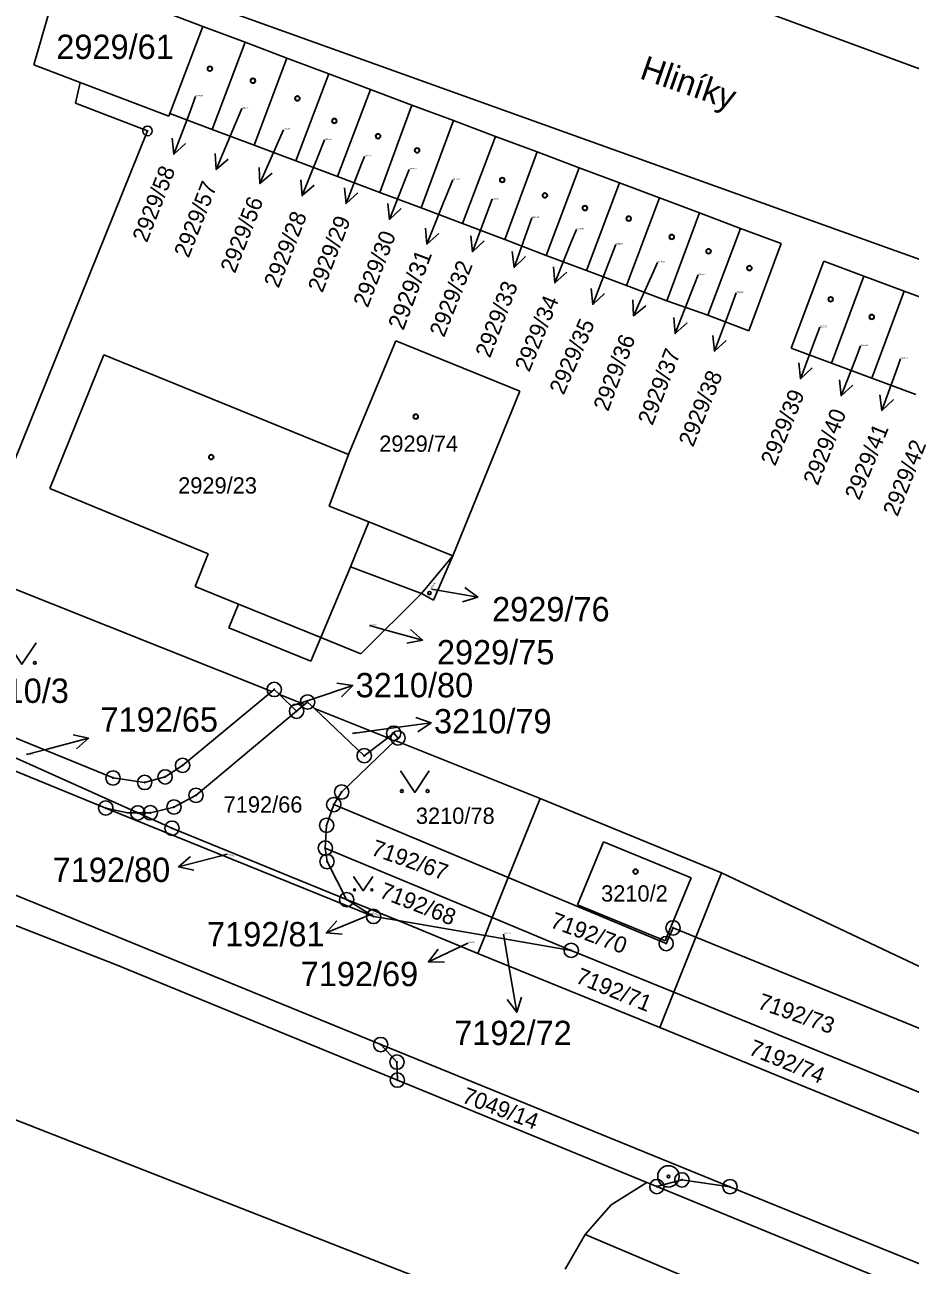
# Model space of a CAD drawing. Extents: x -593183 to -588034, y -1130415 to -1124994.
# Drawn here: x -592005.2 to -591943.3, y -1128267.2 to -1128180.5 of the extents above; entities that cross this region are included whole.
import ezdxf

# ---------------------------------------------------------------- set-up
doc = ezdxf.new("R2010")
doc.units = 0
for name, color, linetype in [('Vrstva 1', 7, 'Continuous'), ('Vrstva 15', 7, 'Continuous'), ('Vrstva 16', 7, 'Continuous'), ('Vrstva 18', 7, 'Continuous'), ('Vrstva 19', 7, 'Continuous'), ('Vrstva 24', 7, 'Continuous'), ('Vrstva 25', 7, 'Continuous'), ('Vrstva 4', 7, 'Continuous')]:
    doc.layers.add(name, color=color, linetype=linetype)

msp = doc.modelspace()

# ---------------------------------------------------------------- linework, layer by layer
at = {"layer": 'Vrstva 1'}
for p, q in [((-591999.24, -1128162.62), (-591935.86, -1128186.03)), ((-592002.65, -1128176.79), (-592004.53, -1128183.25)), ((-591999.4, -1128176.48), (-591937.35, -1128198.75)), ((-591999.73, -1128177.9), (-591992.72, -1128180.57)), ((-591992.72, -1128180.57), (-591995.01, -1128186.66)), ((-591992.72, -1128180.57), (-591989.76, -1128181.68)), ((-591989.76, -1128181.68), (-591992.05, -1128187.77)), ((-591989.76, -1128181.68), (-591986.83, -1128182.79)), ((-592004.53, -1128183.25), (-592001.28, -1128184.49)), ((-591986.83, -1128182.79), (-591989.12, -1128188.87)), ((-591983.9, -1128183.89), (-591986.83, -1128182.79)), ((-591986.21, -1128189.97), (-591983.9, -1128183.89)), ((-591983.9, -1128183.89), (-591980.99, -1128184.98)), ((-592001.28, -1128184.49), (-592001.62, -1128185.95)), ((-592001.28, -1128184.49), (-591995.08, -1128186.84)), ((-591980.99, -1128184.98), (-591983.3, -1128191.07)), ((-591980.99, -1128184.98), (-591978.09, -1128186.07)), ((-592001.62, -1128185.95), (-591996.58, -1128187.88)), ((-591995.08, -1128186.84), (-591995.01, -1128186.66)), ((-591995.01, -1128186.66), (-591992.05, -1128187.77)), ((-591978.09, -1128186.07), (-591980.35, -1128192.18)), ((-591978.09, -1128186.07), (-591975.18, -1128187.16)), ((-591975.18, -1128187.16), (-591977.45, -1128193.26)), ((-591975.18, -1128187.16), (-591972.26, -1128188.26)), ((-591996.58, -1128187.88), (-592009.01, -1128218.65)), ((-591992.05, -1128187.77), (-591989.12, -1128188.87)), ((-591972.26, -1128188.26), (-591974.55, -1128194.35)), ((-591972.26, -1128188.26), (-591969.35, -1128189.35)), ((-591989.12, -1128188.87), (-591986.21, -1128189.97)), ((-591969.35, -1128189.35), (-591971.59, -1128195.46)), ((-591969.35, -1128189.35), (-591966.4, -1128190.46)), ((-591983.3, -1128191.07), (-591986.21, -1128189.97)), ((-591980.35, -1128192.18), (-591983.3, -1128191.07)), ((-591966.4, -1128190.46), (-591968.7, -1128196.59)), ((-591966.4, -1128190.46), (-591963.59, -1128191.51)), ((-591963.59, -1128191.51), (-591965.89, -1128197.64)), ((-591963.59, -1128191.51), (-591960.79, -1128192.56)), ((-591977.45, -1128193.26), (-591980.35, -1128192.18)), ((-591960.79, -1128192.56), (-591963.09, -1128198.69)), ((-591960.79, -1128192.56), (-591957.98, -1128193.61)), ((-591974.55, -1128194.35), (-591977.45, -1128193.26)), ((-591960.28, -1128199.75), (-591957.98, -1128193.61)), ((-591957.98, -1128193.61), (-591955.13, -1128194.69)), ((-591971.59, -1128195.46), (-591974.55, -1128194.35)), ((-591968.7, -1128196.59), (-591971.59, -1128195.46)), ((-591955.13, -1128194.69), (-591957.41, -1128200.77)), ((-591955.13, -1128194.69), (-591952.27, -1128195.76)), ((-591952.27, -1128195.76), (-591954.55, -1128201.85)), ((-591965.89, -1128197.64), (-591968.7, -1128196.59)), ((-591949.3, -1128196.98), (-591951.57, -1128203.07)), ((-591946.49, -1128198.03), (-591949.3, -1128196.98)), ((-591963.09, -1128198.69), (-591965.89, -1128197.64)), ((-591948.76, -1128204.12), (-591946.49, -1128198.03)), ((-591946.49, -1128198.03), (-591943.68, -1128199.08)), ((-591963.09, -1128198.69), (-591960.28, -1128199.75)), ((-591960.28, -1128199.75), (-591957.41, -1128200.77)), ((-591943.68, -1128199.08), (-591945.95, -1128205.17)), ((-591943.68, -1128199.08), (-591940.6, -1128200.22)), ((-591954.55, -1128201.85), (-591957.41, -1128200.77)), ((-591982.53, -1128210.49), (-591979.23, -1128202.56)), ((-591979.23, -1128202.56), (-591970.54, -1128206.08)), ((-591951.57, -1128203.07), (-591948.76, -1128204.12)), ((-591999.63, -1128203.53), (-592003.42, -1128212.88)), ((-591999.63, -1128203.53), (-591982.53, -1128210.49)), ((-591945.95, -1128205.17), (-591948.76, -1128204.12)), ((-591945.95, -1128205.17), (-591942.86, -1128206.31)), ((-591970.54, -1128206.08), (-591975.24, -1128217.57)), ((-591982.53, -1128210.49), (-591983.87, -1128214.1)), ((-592003.42, -1128212.88), (-591992.35, -1128217.45)), ((-591983.87, -1128214.1), (-591981.1, -1128215.21)), ((-591981.1, -1128215.21), (-591982.38, -1128218.36)), ((-592042.06, -1128217.83), (-591999.5, -1128235.21)), ((-591992.35, -1128217.45), (-591993.25, -1128219.73)), ((-591975.24, -1128217.57), (-591977.42, -1128220.22)), ((-591976.58, -1128220.68), (-591975.24, -1128217.57)), ((-592009.01, -1128218.65), (-591987.9, -1128227.07)), ((-591982.38, -1128218.36), (-591984.47, -1128223.3)), ((-591982.38, -1128218.36), (-591977.42, -1128220.22)), ((-591993.25, -1128219.73), (-591990.22, -1128220.96)), ((-591977.42, -1128220.22), (-591981.67, -1128224.44)), ((-591977.42, -1128220.22), (-591976.58, -1128220.68)), ((-591990.22, -1128220.96), (-591990.9, -1128222.61)), ((-591990.9, -1128222.61), (-591985.16, -1128224.95)), ((-591985.16, -1128224.95), (-591984.47, -1128223.3)), ((-591984.47, -1128223.3), (-591981.67, -1128224.44)), ((-592012.61, -1128227.55), (-591998.99, -1128233.11)), ((-591994.13, -1128232.23), (-591987.9, -1128227.07)), ((-591987.9, -1128227.07), (-591987.72, -1128226.92)), ((-591987.72, -1128226.92), (-591987.35, -1128227.28)), ((-591987.35, -1128227.28), (-591986.16, -1128228.44)), ((-591985.6, -1128227.98), (-591987.35, -1128227.28)), ((-591986.16, -1128228.44), (-591985.6, -1128227.98)), ((-591985.6, -1128227.98), (-591985.39, -1128227.8)), ((-591985.39, -1128227.8), (-591984.91, -1128228.26)), ((-591984.91, -1128228.26), (-591981.43, -1128231.55)), ((-591984.91, -1128228.26), (-591979.79, -1128230.3)), ((-592012.99, -1128228.49), (-591997.26, -1128235.55)), ((-591993.19, -1128234.32), (-591986.16, -1128228.44)), ((-592035.07, -1128229.36), (-591980.28, -1128251.74)), ((-591979.79, -1128230.3), (-591979.37, -1128229.98)), ((-591979.37, -1128229.98), (-591979.07, -1128230.31)), ((-592038.06, -1128230.79), (-591998.83, -1128246.15)), ((-591979.27, -1128230.5), (-591983.01, -1128234.09)), ((-591981.43, -1128231.55), (-591979.79, -1128230.3)), ((-591979.07, -1128230.31), (-591979.27, -1128230.5)), ((-591969.14, -1128234.54), (-591979.27, -1128230.5)), ((-591995.35, -1128233.03), (-591994.13, -1128232.23)), ((-591998.99, -1128233.11), (-591996.78, -1128233.42)), ((-591996.78, -1128233.42), (-591995.35, -1128233.03)), ((-591994.73, -1128235.14), (-591993.19, -1128234.32)), ((-591983.01, -1128234.09), (-591983.56, -1128234.97)), ((-591999.5, -1128235.21), (-591997.97, -1128235.55)), ((-591999.5, -1128235.21), (-591980.78, -1128242.79)), ((-591996.38, -1128235.54), (-591994.73, -1128235.14)), ((-591983.56, -1128234.97), (-591984.06, -1128236.42)), ((-591983.56, -1128234.97), (-591971.36, -1128240.07)), ((-591971.36, -1128240.07), (-591969.14, -1128234.54)), ((-591969.14, -1128234.54), (-591956.45, -1128239.73)), ((-591997.97, -1128235.55), (-591997.26, -1128235.55)), ((-591997.26, -1128235.55), (-591996.38, -1128235.54)), ((-591997.26, -1128235.55), (-591994.87, -1128236.62)), ((-591994.87, -1128236.62), (-591982.66, -1128241.61)), ((-591984.06, -1128236.42), (-591984.15, -1128238.01)), ((-591984.15, -1128238.01), (-591984.03, -1128238.95)), ((-591984.15, -1128238.01), (-591972.48, -1128242.87)), ((-591982.66, -1128241.61), (-591984.03, -1128238.95)), ((-591972.48, -1128242.87), (-591971.36, -1128240.07)), ((-591971.36, -1128240.07), (-591960.32, -1128244.68)), ((-591956.45, -1128239.73), (-591958.25, -1128244.24)), ((-591924.05, -1128255.1), (-591956.45, -1128239.73)), ((-591982.66, -1128241.61), (-591979.06, -1128243.08)), ((-591980.78, -1128242.79), (-591982.66, -1128241.61)), ((-591979.06, -1128243.08), (-591980.78, -1128242.79)), ((-591979.06, -1128243.08), (-591972.98, -1128244.13)), ((-591979.06, -1128243.08), (-591973.48, -1128245.37)), ((-591972.98, -1128244.13), (-591972.48, -1128242.87)), ((-591972.48, -1128242.87), (-591966.96, -1128245.16)), ((-591960.32, -1128244.68), (-591959.84, -1128243.59)), ((-591959.84, -1128243.59), (-591958.25, -1128244.24)), ((-591973.48, -1128245.37), (-591972.98, -1128244.13)), ((-591972.98, -1128244.13), (-591966.96, -1128245.16)), ((-591959.78, -1128248.09), (-591958.25, -1128244.24)), ((-591958.25, -1128244.24), (-591940.64, -1128251.42)), ((-591973.48, -1128245.37), (-591960.77, -1128250.56)), ((-591966.96, -1128245.16), (-591959.78, -1128248.09)), ((-591998.83, -1128246.15), (-591979.11, -1128254.23)), ((-591960.77, -1128250.56), (-591959.78, -1128248.09)), ((-591959.78, -1128248.09), (-591942.19, -1128255.26)), ((-591960.77, -1128250.56), (-591927.72, -1128264.08)), ((-591980.28, -1128251.74), (-591979.14, -1128252.97)), ((-591980.28, -1128251.74), (-591955.86, -1128261.68)), ((-591979.14, -1128252.97), (-591979.11, -1128254.23)), ((-591979.11, -1128254.23), (-591961.68, -1128261.38)), ((-592007.9, -1128256.18), (-591975.11, -1128269.03)), ((-591960.97, -1128261.67), (-591959.22, -1128261.2)), ((-591959.22, -1128261.2), (-591955.86, -1128261.68)), ((-591961.68, -1128261.38), (-591964.16, -1128262.95)), ((-591961.68, -1128261.38), (-591960.97, -1128261.67)), ((-591960.97, -1128261.67), (-591931.65, -1128273.68)), ((-591955.86, -1128261.68), (-591814.3, -1128319.36)), ((-591964.16, -1128262.95), (-591965.98, -1128265.01)), ((-591965.98, -1128265.01), (-591967.38, -1128267.44)), ((-591965.98, -1128265.01), (-591946.82, -1128273.12))]:
    msp.add_line(p, q, dxfattribs=at)
at = {"layer": 'Vrstva 16'}
for p, q in [((-591993.22, -1128185.47), (-591993.68, -1128186.7)), ((-591989.99, -1128186.32), (-591990.62, -1128187.81)), ((-591987.08, -1128187.8), (-591987.52, -1128188.81)), ((-591984.21, -1128188.51), (-591984.66, -1128189.62)), ((-591981.41, -1128189.66), (-591981.61, -1128190.17)), ((-591978.29, -1128190.57), (-591978.57, -1128191.27)), ((-591975.23, -1128191.29), (-591975.93, -1128193.01)), ((-591972.49, -1128192.66), (-591972.81, -1128193.52)), ((-591969.71, -1128193.96), (-591969.94, -1128194.6)), ((-591966.6, -1128194.76), (-591966.98, -1128195.71)), ((-591963.85, -1128195.82), (-591964.38, -1128197.2)), ((-591960.92, -1128197.07), (-591961.37, -1128198.07)), ((-591958.08, -1128197.95), (-591958.59, -1128199.25)), ((-591955.42, -1128199.2), (-591955.89, -1128200.47)), ((-591949.58, -1128201.6), (-591949.88, -1128202.4)), ((-591946.73, -1128202.91), (-591947, -1128203.6)), ((-591943.93, -1128203.81), (-591944.22, -1128204.61)), ((-591976.73, -1128219.91), (-591976.45, -1128219.96)), ((-591981.07, -1128222.46), (-591980.25, -1128222.68)), ((-591986.43, -1128228.04), (-591985.08, -1128227.59)), ((-591982.24, -1128229.99), (-591979.73, -1128229.65)), ((-592005.05, -1128231.47), (-592003.6, -1128231.09)), ((-591991.02, -1128238.44), (-591991.52, -1128238.57)), ((-591980.85, -1128242.6), (-591981.31, -1128242.79)), ((-591971.69, -1128244.02), (-591971.27, -1128246.53)), ((-591974.17, -1128244.65), (-591974.23, -1128244.68))]:
    msp.add_line(p, q, dxfattribs=at)
at = {"layer": 'Vrstva 24'}
for centre, radius in [((-591996.58, -1128187.88), 0.335), ((-591996.58, -1128187.88), 0.0219), ((-591987.72, -1128226.92), 0.5), ((-591987.72, -1128226.92), 0.0327), ((-591985.39, -1128227.8), 0.5), ((-591986.16, -1128228.44), 0.5), ((-591986.16, -1128228.44), 0.0327), ((-591985.39, -1128227.8), 0.0327), ((-591979.37, -1128229.98), 0.5), ((-591979.07, -1128230.31), 0.5), ((-591979.37, -1128229.98), 0.0327), ((-591979.07, -1128230.31), 0.0327), ((-591994.13, -1128232.23), 0.5), ((-591981.43, -1128231.55), 0.5), ((-591981.43, -1128231.55), 0.0327), ((-591998.99, -1128233.11), 0.5), ((-591995.35, -1128233.03), 0.5), ((-591994.13, -1128232.23), 0.0327), ((-591998.99, -1128233.11), 0.0327), ((-591996.78, -1128233.42), 0.5), ((-591996.78, -1128233.42), 0.0327), ((-591995.35, -1128233.03), 0.0327), ((-591983.01, -1128234.09), 0.5), ((-591993.19, -1128234.32), 0.5), ((-591993.19, -1128234.32), 0.0327), ((-591983.56, -1128234.97), 0.5), ((-591983.01, -1128234.09), 0.0327), ((-591999.5, -1128235.21), 0.5), ((-591999.5, -1128235.21), 0.0327), ((-591997.26, -1128235.55), 0.5), ((-591996.38, -1128235.54), 0.5), ((-591994.73, -1128235.14), 0.5), ((-591994.73, -1128235.14), 0.0327), ((-591983.56, -1128234.97), 0.0327), ((-591997.26, -1128235.55), 0.0327), ((-591996.38, -1128235.54), 0.0327), ((-591994.87, -1128236.62), 0.5), ((-591984.06, -1128236.42), 0.5), ((-591994.87, -1128236.62), 0.0327), ((-591984.06, -1128236.42), 0.0327), ((-591984.15, -1128238.01), 0.5), ((-591984.03, -1128238.95), 0.5), ((-591984.15, -1128238.01), 0.0327), ((-591984.03, -1128238.95), 0.0327), ((-591982.66, -1128241.61), 0.5), ((-591982.66, -1128241.61), 0.0327), ((-591980.78, -1128242.79), 0.5), ((-591980.78, -1128242.79), 0.0327), ((-591959.84, -1128243.59), 0.5), ((-591959.84, -1128243.59), 0.0327), ((-591966.96, -1128245.16), 0.5), ((-591960.32, -1128244.68), 0.5), ((-591960.32, -1128244.68), 0.0327), ((-591966.96, -1128245.16), 0.0327), ((-591980.28, -1128251.74), 0.5), ((-591980.28, -1128251.74), 0.0327), ((-591979.14, -1128252.97), 0.5), ((-591979.14, -1128252.97), 0.0327), ((-591979.11, -1128254.23), 0.5), ((-591979.11, -1128254.23), 0.0327), ((-591960.16, -1128260.96), 0.75), ((-591960.97, -1128261.67), 0.5), ((-591960.16, -1128260.96), 0.0903), ((-591959.22, -1128261.2), 0.5), ((-591959.22, -1128261.2), 0.0327), ((-591955.86, -1128261.68), 0.5), ((-591960.97, -1128261.67), 0.0327), ((-591955.86, -1128261.68), 0.0327)]:
    msp.add_circle(centre, radius, dxfattribs=at)
at = {"layer": 'Vrstva 25'}
for p, q in [((-591993.68, -1128186.7), (-591994.736, -1128189.508)), ((-591990.62, -1128187.81), (-591991.782, -1128190.576)), ((-591987.52, -1128188.81), (-591988.726, -1128191.557)), ((-591984.66, -1128189.62), (-591985.774, -1128192.405)), ((-591981.61, -1128190.17), (-591982.702, -1128192.964)), ((-591978.57, -1128191.27), (-591979.673, -1128194.06)), ((-591975.93, -1128193.01), (-591977.06, -1128195.789)), ((-591972.81, -1128193.52), (-591973.859, -1128196.331)), ((-591969.94, -1128194.6), (-591970.952, -1128197.424)), ((-591966.98, -1128195.71), (-591968.106, -1128198.491)), ((-591964.38, -1128197.2), (-591965.452, -1128200.002)), ((-591961.37, -1128198.07), (-591962.608, -1128200.803)), ((-591958.59, -1128199.25), (-591959.683, -1128202.044)), ((-591955.89, -1128200.47), (-591956.931, -1128203.283)), ((-591949.88, -1128202.4), (-591950.938, -1128205.207)), ((-591947, -1128203.6), (-591948.092, -1128206.394)), ((-591944.22, -1128204.61), (-591945.241, -1128207.431)), ((-591976.45, -1128219.96), (-591973.492, -1128220.462)), ((-591980.25, -1128222.68), (-591977.355, -1128223.466)), ((-591985.08, -1128227.59), (-591982.232, -1128226.647)), ((-591979.73, -1128229.65), (-591976.758, -1128229.243)), ((-592003.6, -1128231.09), (-592000.696, -1128230.336)), ((-591991.52, -1128238.57), (-591994.424, -1128239.322)), ((-591981.31, -1128242.79), (-591984.081, -1128243.94)), ((-591974.23, -1128244.68), (-591976.942, -1128245.963)), ((-591971.27, -1128246.53), (-591970.772, -1128249.488))]:
    msp.add_line(p, q, dxfattribs=at)
for points in [[(-591993.916, -1128188.748), (-591994.736, -1128189.508), (-591994.852, -1128188.396)], [(-591990.934, -1128189.848), (-591991.782, -1128190.576), (-591991.856, -1128189.46)], [(-591987.866, -1128190.842), (-591988.726, -1128191.557), (-591988.782, -1128190.441)], [(-591984.939, -1128191.663), (-591985.774, -1128192.405), (-591985.867, -1128191.291)], [(-591981.872, -1128192.215), (-591982.702, -1128192.964), (-591982.804, -1128191.851)], [(-591978.84, -1128193.314), (-591979.673, -1128194.06), (-591979.77, -1128192.946)], [(-591976.22, -1128195.051), (-591977.06, -1128195.789), (-591977.147, -1128194.674)], [(-591973.041, -1128195.569), (-591973.859, -1128196.331), (-591973.978, -1128195.219)], [(-591970.144, -1128196.651), (-591970.952, -1128197.424), (-591971.085, -1128196.314)], [(-591967.267, -1128197.751), (-591968.106, -1128198.491), (-591968.194, -1128197.376)], [(-591964.628, -1128199.247), (-591965.452, -1128200.002), (-591965.562, -1128198.889)], [(-591961.74, -1128200.098), (-591962.608, -1128200.803), (-591962.651, -1128199.685)], [(-591958.853, -1128201.295), (-591959.683, -1128202.044), (-591959.784, -1128200.93)], [(-591956.115, -1128202.519), (-591956.931, -1128203.283), (-591957.053, -1128202.172)], [(-591950.117, -1128204.448), (-591950.938, -1128205.207), (-591951.053, -1128204.095)], [(-591947.262, -1128205.645), (-591948.092, -1128206.394), (-591948.194, -1128205.281)], [(-591944.43, -1128206.661), (-591945.241, -1128207.431), (-591945.371, -1128206.321)], [(-591974.395, -1128219.802), (-591973.492, -1128220.462), (-591974.562, -1128220.788)], [(-591978.189, -1128222.722), (-591977.355, -1128223.466), (-591978.451, -1128223.687)], [(-592004.36, -1128223.66), (-592005.36, -1128225.16), (-592006.36, -1128223.66)], [(-591983.338, -1128226.487), (-591982.232, -1128226.647), (-591983.024, -1128227.436)], [(-591977.816, -1128228.883), (-591976.758, -1128229.243), (-591977.681, -1128229.874)], [(-592001.79, -1128230.103), (-592000.696, -1128230.336), (-592001.539, -1128231.071)], [(-591976.9, -1128232.62), (-591977.9, -1128234.12), (-591978.9, -1128232.62)], [(-591993.331, -1128239.555), (-591994.424, -1128239.322), (-591993.581, -1128238.587)], [(-591980.83, -1128239.985), (-591981.5, -1128240.99), (-591982.17, -1128239.985)], [(-591982.966, -1128244.018), (-591984.081, -1128243.94), (-591983.349, -1128243.095)], [(-591975.824, -1128245.987), (-591976.942, -1128245.963), (-591976.252, -1128245.083)], [(-591970.445, -1128248.419), (-591970.772, -1128249.488), (-591971.431, -1128248.585)]]:
    msp.add_lwpolyline(points, dxfattribs=at)
for centre, radius in [((-591992.22, -1128183.53), 0.175), ((-591992.22, -1128183.53), 0.15), ((-591989.21, -1128184.37), 0.175), ((-591989.21, -1128184.37), 0.15), ((-591986.1, -1128185.61), 0.175), ((-591986.1, -1128185.61), 0.15), ((-591983.52, -1128187.18), 0.175), ((-591983.52, -1128187.18), 0.15), ((-591980.46, -1128188.25), 0.175), ((-591980.46, -1128188.25), 0.15), ((-591977.73, -1128189.24), 0.175), ((-591977.73, -1128189.24), 0.15), ((-591971.78, -1128191.31), 0.175), ((-591971.78, -1128191.31), 0.15), ((-591968.8, -1128192.39), 0.175), ((-591968.8, -1128192.39), 0.15), ((-591966, -1128193.27), 0.175), ((-591966, -1128193.27), 0.15), ((-591962.94, -1128194.01), 0.175), ((-591962.94, -1128194.01), 0.15), ((-591959.93, -1128195.29), 0.175), ((-591959.93, -1128195.29), 0.15), ((-591957.36, -1128196.29), 0.175), ((-591957.36, -1128196.29), 0.15), ((-591954.5, -1128197.47), 0.175), ((-591954.5, -1128197.47), 0.15), ((-591948.82, -1128199.65), 0.175), ((-591948.82, -1128199.65), 0.15), ((-591945.95, -1128200.88), 0.175), ((-591945.95, -1128200.88), 0.15), ((-591977.83, -1128207.85), 0.175), ((-591977.83, -1128207.85), 0.15), ((-591992.13, -1128210.68), 0.175), ((-591992.13, -1128210.68), 0.15), ((-591976.87, -1128220.18), 0.117), ((-591976.87, -1128220.18), 0.101), ((-592004.46, -1128225.06), 0.1), ((-591978.8, -1128234.02), 0.1), ((-591977, -1128234.02), 0.1), ((-591962.46, -1128239.65), 0.175), ((-591962.46, -1128239.65), 0.15), ((-591982.103, -1128240.923), 0.067), ((-591980.897, -1128240.923), 0.067)]:
    msp.add_circle(centre, radius, dxfattribs=at)
at = {"layer": 'Vrstva 4'}
for p, q in [((-591981.1, -1128215.21), (-591975.24, -1128217.57)), ((-591990.22, -1128220.96), (-591984.47, -1128223.3)), ((-591966.51, -1128241.97), (-591964.7, -1128237.57)), ((-591958.57, -1128240.1), (-591964.7, -1128237.57)), ((-591960.38, -1128244.5), (-591958.57, -1128240.1)), ((-591966.51, -1128241.97), (-591960.38, -1128244.5))]:
    msp.add_line(p, q, dxfattribs=at)

# ---------------------------------------------------------------- texts
at = {"layer": 'Vrstva 15'}
msp.add_text('Hliníky', height=1.7, rotation=340.92486, dxfattribs=at).set_placement((-591962.25, -1128184.19))
at = {"layer": 'Vrstva 16'}
for s, height, rotation, p in [('2929/58', 1.14, 68.65893, (-591996.62, -1128195.74)), ('2929/57', 1.14, 68.51943, (-591993.71, -1128196.82)), ('2929/56', 1.14, 68.6466, (-591990.47, -1128197.89)), ('2929/28', 1.14, 68.63895, (-591987.42, -1128198.92)), ('2929/29', 1.14, 68.82741, (-591984.35, -1128199.24)), ('2929/30', 1.14, 68.84487, (-591981.18, -1128200.29)), ('2929/31', 1.19, 69.444, (-591978.69, -1128201.87)), ('2929/32', 1.14, 68.42349, (-591975.85, -1128202.36)), ('2929/33', 1.14, 69.00858, (-591972.64, -1128203.81)), ('2929/34', 1.14, 67.69377, (-591969.89, -1128204.79)), ('2929/35', 1.14, 66.42954, (-591967.49, -1128206.39)), ('2929/36', 1.14, 69.53247, (-591964.38, -1128207.54)), ('2929/37', 1.14, 68.88402, (-591961.28, -1128208.52)), ('2929/38', 1.14, 67.79655, (-591958.44, -1128210.03)), ('2929/39', 1.14, 67.75101, (-591952.7, -1128211.36)), ('2929/40', 1.14, 68.48415, (-591949.72, -1128212.72)), ('2929/41', 1.14, 67.85199, (-591946.82, -1128213.76)), ('2929/42', 1.14, 68.34843, (-591944.15, -1128214.89))]:
    msp.add_text(s, height=height, rotation=rotation, dxfattribs=at).set_placement(p)
for s, p in [('2929/76', (-591972.49, -1128222.16)), ('2929/75', (-591976.35, -1128225.17)), ('3210/80', (-591982.03, -1128227.47)), ('7192/65', (-591999.87, -1128229.88)), ('3210/79', (-591976.55, -1128229.99)), ('7192/80', (-592003.211, -1128240.38)), ('7192/81', (-591992.419, -1128244.88)), ('7192/69', (-591985.876, -1128247.66)), ('7192/72', (-591975.14, -1128251.78))]:
    msp.add_text(s, height=1.7, dxfattribs=at).set_placement(p)
at = {"layer": 'Vrstva 18'}
for s, height, p in [('2929/31', 0.1, (-591975.23, -1128191.29)), ('2929/75', 0.1, (-591981.07, -1128222.46)), ('3210/3', 1.7, (-592009.03, -1128227.86)), ('3210/80', 0.1, (-591986.43, -1128228.04)), ('3210/79', 0.1, (-591982.24, -1128229.99)), ('7192/65', 0.1, (-592005.05, -1128231.47)), ('7192/66', 1.14, (-591991.26, -1128235.53)), ('3210/78', 1.14, (-591977.82, -1128236.32)), ('7192/72', 0.1, (-591971.69, -1128244.02)), ('7192/69', 0.1, (-591974.17, -1128244.65))]:
    msp.add_text(s, height=height, dxfattribs=at).set_placement(p)
for s, height, rotation, p in [('7192/67', 1.14, 340.65063, (-591981.02, -1128238.46)), ('7192/80', 0.1, 336.50145, (-591991.02, -1128238.44)), ('7192/68', 1.14, 338.58702, (-591980.44, -1128241.43)), ('7192/81', 0.1, 341.02962, (-591980.85, -1128242.6)), ('7192/70', 1.14, 339.80211, (-591968.5, -1128243.52)), ('7192/71', 1.14, 337.74057, (-591966.73, -1128247.39)), ('7192/73', 1.14, 340.73955, (-591954, -1128249.2)), ('7192/74', 1.14, 337.51368, (-591954.63, -1128252.4)), ('7049/14', 1.14, 339.32844, (-591974.67, -1128255.76))]:
    msp.add_text(s, height=height, rotation=rotation, dxfattribs=at).set_placement(p)
at = {"layer": 'Vrstva 19'}
for s, height, p in [('2929/61', 1.7, (-592002.96, -1128182.85)), ('2929/58', 0.1, (-591993.22, -1128185.47)), ('2929/57', 0.1, (-591989.99, -1128186.32)), ('2929/56', 0.1, (-591987.08, -1128187.8)), ('2929/28', 0.1, (-591984.21, -1128188.51)), ('2929/29', 0.1, (-591981.41, -1128189.66)), ('2929/30', 0.1, (-591978.29, -1128190.57)), ('2929/32', 0.1, (-591972.49, -1128192.66)), ('2929/33', 0.1, (-591969.71, -1128193.96)), ('2929/34', 0.1, (-591966.6, -1128194.76)), ('2929/35', 0.1, (-591963.85, -1128195.82)), ('2929/36', 0.1, (-591960.92, -1128197.07)), ('2929/37', 0.1, (-591958.08, -1128197.95)), ('2929/38', 0.1, (-591955.42, -1128199.2)), ('2929/39', 0.1, (-591949.58, -1128201.6)), ('2929/40', 0.1, (-591946.73, -1128202.91)), ('2929/41', 0.1, (-591943.93, -1128203.81)), ('2929/74', 1.14, (-591980.38, -1128210.31)), ('2929/23', 1.14, (-591994.44, -1128213.23)), ('3210/2', 1.14, (-591964.87, -1128241.75))]:
    msp.add_text(s, height=height, dxfattribs=at).set_placement(p)
msp.add_text('2929/76', height=0.1, rotation=55.17549, dxfattribs=at).set_placement((-591976.73, -1128219.91))

doc.saveas('drawing.dxf')
